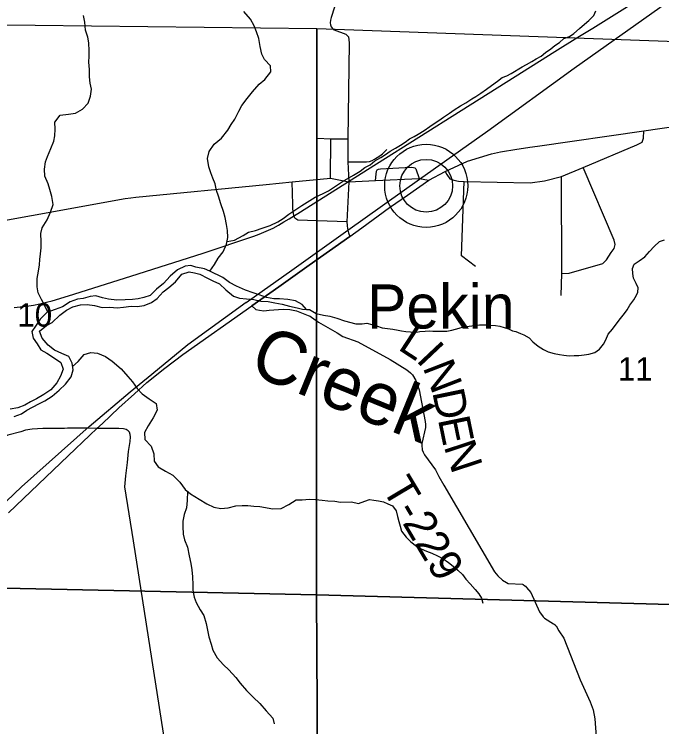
# Model space of a CAD drawing. Extents: x 0 to 34, y 0 to 22.
# Drawn here: x 3.716 to 4.875, y 15.27 to 16.545 of the extents above; entities that cross this region are included whole.
import ezdxf

# ---------------------------------------------------------------- set-up
doc = ezdxf.new("R2010")
doc.units = 0
doc.layers.add('Default', color=7, linetype='Continuous')

msp = doc.modelspace()

# ---------------------------------------------------------------- linework, layer by layer
at = {"layer": 'Default'}
for p, q in [((4.2817, 16.2516), (4.2827, 16.3216)), ((4.4533, 16.2382), (4.4533, 16.2382)), ((4.0219, 15.0104), (3.9291, 15.6027))]:
    msp.add_line(p, q, dxfattribs=at)
for points in [[(4.1345, 17.0111), (4.1482, 16.9849), (4.2622, 16.918), (4.2732, 16.9148), (4.2816, 16.9142), (4.341, 16.9149), (4.3454, 16.9137), (4.3498, 16.9116), (4.3533, 16.9088), (4.3596, 16.9011), (4.3625, 16.8954), (4.368, 16.8832), (4.3739, 16.8636), (4.3756, 16.8563), (4.3768, 16.846), (4.3762, 16.8394), (4.3746, 16.8279), (4.3721, 16.8159), (4.2834, 16.5397), (4.2818, 16.5345), (4.2813, 16.5302), (4.2818, 16.5266)], [(4.1311, 16.0292), (4.2125, 16.0873), (4.3131, 16.1587), (4.4414, 16.2501), (4.5633, 16.3368), (4.7182, 16.4485), (4.8857, 16.5673), (5.0019, 16.6486), (5.1164, 16.7282), (5.2393, 16.8153)], [(3.7156, 16.0206), (3.7263, 16.0214), (3.7379, 16.0226), (3.7504, 16.0245), (3.7616, 16.0267), (3.7736, 16.0296), (3.7838, 16.0323), (3.8128, 16.0412), (3.9246, 16.0764), (4.0541, 16.1175), (4.1445, 16.1478), (4.154, 16.1514), (4.1626, 16.1549), (4.1709, 16.1586), (4.1793, 16.1626), (4.1891, 16.1679), (4.1985, 16.1736), (4.2079, 16.179), (4.228, 16.1913), (4.2464, 16.2028), (4.3645, 16.2774), (4.5159, 16.3728), (4.6122, 16.4336), (4.6833, 16.4784), (4.7249, 16.504), (4.7515, 16.5202), (4.8736, 16.5975)], [(4.0662, 16.0852), (4.074, 16.0974), (4.081, 16.1085), (4.0895, 16.12), (4.096, 16.1338), (4.0981, 16.1456), (4.0975, 16.1581), (4.0955, 16.1687), (4.0934, 16.1815), (4.0902, 16.1924), (4.0854, 16.206), (4.0814, 16.2196), (4.0778, 16.2298), (4.0757, 16.2415), (4.0714, 16.2517), (4.0675, 16.2615), (4.0643, 16.272), (4.0618, 16.2868), (4.0646, 16.2997), (4.0738, 16.3127), (4.0865, 16.3235), (4.098, 16.3378), (4.1042, 16.3477), (4.1109, 16.3577), (4.1178, 16.3718), (4.1229, 16.3818), (4.1329, 16.3944), (4.1422, 16.4063), (4.1544, 16.4202), (4.1641, 16.4287), (4.1752, 16.4421), (4.1743, 16.4527), (4.1635, 16.4643), (4.1592, 16.4741), (4.1563, 16.4877), (4.1535, 16.5017), (4.1495, 16.5137), (4.1455, 16.5243), (4.1389, 16.5363), (4.1269, 16.5505)], [(4.3233, 16.2574), (4.3349, 16.2642), (4.3436, 16.2707), (4.353, 16.2758), (4.3612, 16.2828), (4.3718, 16.2886), (4.3801, 16.294), (4.3887, 16.2999), (4.3981, 16.3053), (4.4071, 16.3111), (4.4158, 16.3166), (4.4233, 16.3224), (4.4316, 16.3263), (4.4391, 16.3306), (4.4493, 16.3372), (4.4595, 16.3445), (4.4677, 16.35), (4.4756, 16.355), (4.4843, 16.3612), (4.4948, 16.3682), (4.5034, 16.3744), (4.5144, 16.3814), (4.5242, 16.3868), (4.5347, 16.3938), (4.5422, 16.3981), (4.5509, 16.4039), (4.561, 16.4109), (4.57, 16.4175), (4.5809, 16.4256), (4.5892, 16.4318), (4.5975, 16.435), (4.6054, 16.4392), (4.625, 16.4509), (4.6329, 16.4556), (4.6423, 16.4607), (4.6502, 16.4653), (4.6593, 16.47), (4.6668, 16.4766), (4.6762, 16.4832), (4.6833, 16.4893), (4.6916, 16.4948), (4.6998, 16.5017), (4.7096, 16.5053), (4.7175, 16.5107), (4.7277, 16.5196), (4.7367, 16.5273), (4.7446, 16.5339), (4.7532, 16.5431), (4.7568, 16.5515)], [(3.7762, 16.012), (3.771, 16.0223), (3.7643, 16.0347), (3.7588, 16.0468), (3.7571, 16.0574), (3.7569, 16.0725), (3.7593, 16.0855), (3.761, 16.0965), (3.7616, 16.106), (3.7626, 16.1166), (3.7639, 16.1272), (3.7641, 16.1378), (3.7631, 16.1526), (3.766, 16.1629), (3.7748, 16.1771), (3.7806, 16.1912), (3.7857, 16.2049), (3.7828, 16.2189), (3.7796, 16.2317), (3.7768, 16.2419), (3.7705, 16.2555), (3.7699, 16.268), (3.7716, 16.2813), (3.7756, 16.2908), (3.7814, 16.3049), (3.7869, 16.3183), (3.7886, 16.3278), (3.7888, 16.3395), (3.7886, 16.3521), (3.7982, 16.3647), (3.8129, 16.3665), (3.8257, 16.3682), (3.8377, 16.3752), (3.8481, 16.3864), (3.8524, 16.3986), (3.8541, 16.4111), (3.8517, 16.4217), (3.8507, 16.4331), (3.8505, 16.4463), (3.8495, 16.4596), (3.8497, 16.4702), (3.8499, 16.48), (3.8493, 16.4944), (3.8477, 16.5043), (3.8433, 16.5171), (3.8419, 16.5311), (3.8395, 16.5432)], [(4.2818, 16.5266), (4.2833, 16.523), (4.2839, 16.5222), (4.2856, 16.5199), (4.2884, 16.5174), (4.3091, 16.5096), (4.3141, 16.5047), (4.3151, 16.494), (4.313, 16.3218), (4.3132, 16.2809), (4.3145, 16.2453), (4.3114, 16.1734), (4.3116, 16.1672), (4.3121, 16.1609), (4.3144, 16.1542), (4.3166, 16.1475)], [(4.6523, 16.309), (4.8427, 16.3364), (4.9041, 16.3453), (4.9289, 16.3504), (4.9478, 16.3556), (4.9699, 16.364), (4.9932, 16.3745), (5.0136, 16.3866), (5.037, 16.4037), (5.0592, 16.4236), (5.0737, 16.4394), (5.0873, 16.4557), (5.1077, 16.4842)], [(2.7536, 16.3903), (2.9496, 16.3731), (3.0622, 16.4028), (3.0755, 16.4054), (3.0886, 16.4068), (3.1054, 16.4056), (3.1194, 16.4032), (3.1332, 16.3974), (3.1463, 16.3874), (3.161, 16.3732), (3.1758, 16.3541), (3.3304, 16.1487), (3.3378, 16.1413), (3.3458, 16.1357), (3.3589, 16.1287), (3.3749, 16.1245), (3.3922, 16.1234), (3.4105, 16.1244), (3.9144, 16.2154), (3.9245, 16.2165), (3.9335, 16.2176), (4.1665, 16.2407)], [(4.6394, 16.2438), (4.6653, 16.2471), (4.6956, 16.255), (4.7341, 16.2712), (4.83, 16.3114), (4.8396, 16.3164), (4.8423, 16.3232), (4.8427, 16.3364)], [(4.313, 16.3218), (4.2827, 16.3216), (4.2582, 16.3228)], [(4.3132, 16.2809), (4.3462, 16.2813), (4.3519, 16.2818), (4.3564, 16.2834), (4.3606, 16.2856), (4.3654, 16.2889), (4.37, 16.2919), (4.3752, 16.2956), (4.3825, 16.3031)], [(4.5863, 16.2989), (4.5901, 16.2997), (4.6118, 16.3032), (4.639, 16.3071), (4.6523, 16.309)], [(4.3166, 16.1475), (4.3383, 16.1629), (4.3873, 16.1991), (4.4195, 16.2212), (4.4582, 16.2482), (4.4869, 16.2639), (4.5271, 16.2822), (4.5486, 16.289), (4.5701, 16.2953), (4.5863, 16.2989)], [(4.3627, 16.2476), (4.3634, 16.2593), (4.3644, 16.2646), (4.3656, 16.2666), (4.3666, 16.2672), (4.368, 16.2678), (4.3717, 16.2685), (4.4261, 16.2714), (4.4307, 16.2712), (4.4329, 16.2704), (4.4346, 16.2688), (4.4404, 16.2513)], [(4.4869, 16.2639), (4.4901, 16.2584), (4.4956, 16.2509), (4.5029, 16.248), (4.5109, 16.2465), (4.5212, 16.2459), (4.6394, 16.2438)], [(4.7692, 16.0988), (4.776, 16.1058), (4.7846, 16.1186), (4.7896, 16.1258), (4.7916, 16.1333), (4.7896, 16.1409), (4.7341, 16.2712)], [(4.0968, 16.1382), (4.1099, 16.1408), (4.1256, 16.1491), (4.1354, 16.1549), (4.1474, 16.1581), (4.1598, 16.1625), (4.1741, 16.1669), (4.1876, 16.1736), (4.1973, 16.1798), (4.2074, 16.1872), (4.2179, 16.1945), (4.2306, 16.2031), (4.2448, 16.212), (4.2545, 16.2179), (4.2688, 16.2245), (4.2785, 16.2293), (4.2927, 16.239), (4.3032, 16.246), (4.3233, 16.2574)], [(4.1665, 16.2407), (4.2133, 16.2453), (4.2817, 16.2516), (4.3145, 16.2453), (4.3627, 16.2476), (4.4404, 16.2513), (4.4582, 16.2482)], [(4.6951, 16.042), (4.6958, 16.0812), (4.6956, 16.255)], [(4.216, 16.1852), (4.2143, 16.1969), (4.2143, 16.2046), (4.2133, 16.2453)], [(4.5415, 16.0936), (4.5166, 16.1128), (4.5212, 16.2459)], [(4.3114, 16.1734), (4.2233, 16.1766), (4.218, 16.1802), (4.216, 16.1852)], [(4.1412, 16.0232), (4.1895, 16.0571), (4.2435, 16.096), (4.3166, 16.1475)], [(4.3166, 16.1475), (4.2435, 16.096), (4.1895, 16.0571), (4.1412, 16.0232)], [(4.3274, 15.991), (4.3385, 15.9911), (4.3472, 15.9921), (4.356, 15.9896), (4.3644, 15.9874), (4.3747, 15.9842), (4.3842, 15.9828), (4.3937, 15.9818), (4.4029, 15.98), (4.4089, 15.9786), (4.4169, 15.9772), (4.4253, 15.9765), (4.4363, 15.9763), (4.442, 15.9771), (4.4511, 15.978), (4.4595, 15.9785), (4.4652, 15.9782), (4.475, 15.978), (4.4842, 15.9777), (4.4899, 15.9778), (4.4993, 15.9799), (4.5122, 15.9835), (4.5201, 15.9855), (4.53, 15.9868), (4.5395, 15.988), (4.5485, 15.9893), (4.5546, 15.9894), (4.5634, 15.9891), (4.5691, 15.9888), (4.5774, 15.9882), (4.585, 15.9868), (4.5927, 15.9846), (4.6003, 15.9821), (4.6079, 15.9788), (4.6137, 15.9773), (4.6221, 15.974), (4.6278, 15.9711), (4.6374, 15.9659), (4.6443, 15.9591), (4.6539, 15.9513), (4.6631, 15.9454), (4.6715, 15.9409), (4.6822, 15.938), (4.6917, 15.9363), (4.6997, 15.9349), (4.7092, 15.9339), (4.7183, 15.9344), (4.7267, 15.9345), (4.7362, 15.9354), (4.7445, 15.9367), (4.7551, 15.9398), (4.7634, 15.946), (4.7705, 15.9545), (4.7749, 15.9625), (4.7789, 15.9725), (4.7868, 15.9817), (4.7931, 15.9905), (4.8009, 16.0005), (4.8084, 16.0097), (4.8128, 16.0162), (4.818, 16.0246), (4.8251, 16.0342), (4.8299, 16.0423), (4.8318, 16.048), (4.8324, 16.0556), (4.8292, 16.0635), (4.8246, 16.073), (4.8233, 16.0813), (4.8224, 16.09), (4.8257, 16.098), (4.8347, 16.1039), (4.8445, 16.1108), (4.8531, 16.1208), (4.8613, 16.1293), (4.8711, 16.1385), (4.8798, 16.1417)], [(4.6958, 16.0812), (4.7094, 16.0817), (4.7692, 16.0988)], [(4.2387, 16.0168), (4.2312, 16.0258), (4.219, 16.0321), (4.2057, 16.0345), (4.1909, 16.0358), (4.1807, 16.036), (4.1671, 16.038), (4.1542, 16.0427), (4.1435, 16.0463), (4.1295, 16.0514), (4.1135, 16.0587), (4.1013, 16.0649), (4.089, 16.0742), (4.0661, 16.0852), (4.0562, 16.0896), (4.0411, 16.0927), (4.0316, 16.0956), (4.0218, 16.0943), (4.0083, 16.0876), (3.9949, 16.0764), (3.983, 16.0633), (3.9707, 16.0529), (3.9588, 16.0417), (3.9475, 16.0385), (3.9374, 16.036), (3.9276, 16.0347), (3.9144, 16.0341), (3.8992, 16.0335), (3.8845, 16.0351), (3.8739, 16.0376), (3.8617, 16.0412), (3.8519, 16.0399), (3.8391, 16.0367), (3.8289, 16.035), (3.8158, 16.0306), (3.8023, 16.0216), (3.7892, 16.0165), (3.7742, 16.0113), (3.7619, 15.9993), (3.7538, 15.9871), (3.7472, 15.9775), (3.7496, 15.9654), (3.7566, 15.9553), (3.7636, 15.9444), (3.7739, 15.9385), (3.7858, 15.9307), (3.7991, 15.9219), (3.8035, 15.9102), (3.7988, 15.8976), (3.7918, 15.8857), (3.7811, 15.873), (3.7687, 15.8645), (3.7556, 15.8571), (3.7448, 15.8516), (3.7347, 15.8457), (3.7223, 15.8406), (3.7087, 15.8381)], [(3.7158, 15.8253), (3.7285, 15.8301), (3.7382, 15.8367), (3.76, 15.848), (3.7708, 15.8532), (3.7835, 15.8617), (3.7962, 15.8722), (3.8077, 15.883), (3.8177, 15.8964), (3.8213, 15.909), (3.8192, 15.9207), (3.8137, 15.9324), (3.8007, 15.9382), (3.7878, 15.9437), (3.7763, 15.9526), (3.7655, 15.9653), (3.7611, 15.9777), (3.7738, 15.9882), (3.7839, 15.9936), (3.7973, 16.0068), (3.8092, 16.0157), (3.8205, 16.0216), (3.8344, 16.0252), (3.8465, 16.0258), (3.8597, 16.0237), (3.873, 16.0205), (3.887, 16.0208), (3.9002, 16.0199), (3.9112, 16.0212), (3.9248, 16.0226), (3.9357, 16.0224), (3.9485, 16.0241), (3.9613, 16.0292), (3.9718, 16.0366), (3.9825, 16.0482), (3.9926, 16.0559), (4.0045, 16.0664), (4.016, 16.0798), (4.0291, 16.0842), (4.0386, 16.0825), (4.0481, 16.08), (4.0615, 16.0726), (4.071, 16.0679), (4.0832, 16.0627), (4.0947, 16.0519), (4.1085, 16.0408), (4.1191, 16.0368), (4.1316, 16.0359)], [(4.1316, 16.0359), (4.1445, 16.0346), (4.1574, 16.0314), (4.1702, 16.0309), (4.182, 16.0284), (4.1953, 16.026), (4.2086, 16.0228), (4.2222, 16.0196), (4.2317, 16.0175), (4.2387, 16.0168)], [(2.9993, 14.9996), (3.3253, 15.3142), (3.7288, 15.6994), (3.8497, 15.8071), (3.923, 15.8692), (3.9623, 15.9011), (4.0263, 15.9543), (4.1309, 16.0297)], [(3.8638, 15.8037), (3.8735, 15.8126), (3.9029, 15.8405), (3.931, 15.866), (3.9532, 15.8858), (3.9853, 15.9119), (4.0176, 15.9361), (4.1412, 16.0232)], [(4.1412, 16.0232), (4.1483, 16.017), (4.155, 16.0153), (4.1627, 16.0146), (4.1722, 16.0156), (4.1973, 16.0175), (4.209, 16.0168), (4.2209, 16.0143), (4.2417, 16.0061), (4.2454, 16.0046), (4.2479, 16.003), (4.2605, 15.9943), (4.2939, 15.9748), (4.3039, 15.9682), (4.3306, 15.9588), (4.3888, 15.9271), (4.4187, 15.9088), (4.4252, 15.9036), (4.4287, 15.8998), (4.4344, 15.8896), (4.4384, 15.8794), (4.4404, 15.8732), (4.4513, 15.8163), (4.452, 15.8108), (4.4522, 15.8056), (4.4456, 15.7771), (4.4455, 15.7737), (4.4461, 15.7656), (4.4477, 15.7612), (4.45, 15.7566), (4.4698, 15.7294), (4.4756, 15.7176), (4.4845, 15.7025), (4.5757, 15.5471), (4.5813, 15.5401), (4.5896, 15.5324), (4.5968, 15.5279), (4.5999, 15.5264), (4.6255, 15.5248), (4.6263, 15.5245), (4.6269, 15.5242), (4.628, 15.5235), (4.6307, 15.5212), (4.6328, 15.5191), (4.6405, 15.5101), (4.6561, 15.4756), (4.6625, 15.4666), (4.665, 15.4643), (4.6812, 15.4542), (4.6833, 15.4527), (4.6843, 15.4519), (4.6856, 15.4502), (4.6907, 15.4413), (4.6996, 15.4285), (4.7286, 15.3535), (4.7469, 15.3141), (4.7524, 15.3001), (4.7553, 15.2841), (4.7664, 15.1324)], [(4.2387, 16.0168), (4.2442, 16.0166), (4.2564, 16.0096), (4.2693, 16.0067), (4.281, 16.005), (4.2932, 16.0015), (4.3069, 15.9964), (4.3274, 15.991)], [(3.8203, 15.9146), (3.8305, 15.9239), (3.8408, 15.9362), (3.8529, 15.9395), (3.865, 15.9385), (3.8791, 15.9327), (3.8913, 15.9242), (3.9074, 15.9104), (3.919, 15.897), (3.9275, 15.8873), (3.936, 15.8753), (3.9448, 15.8656), (3.9575, 15.8567), (3.9697, 15.8485), (3.9714, 15.8368), (3.9645, 15.8227), (3.9556, 15.8085), (3.9487, 15.7963), (3.9496, 15.7841), (3.9608, 15.7718), (3.9659, 15.7586), (3.9662, 15.7454), (3.9735, 15.7349), (3.9865, 15.7271), (3.9999, 15.7202), (4.0122, 15.7075), (4.0215, 15.6947), (4.0314, 15.6869), (4.0467, 15.6773), (4.0604, 15.6689), (4.073, 15.663), (4.0855, 15.6602), (4.0987, 15.6619), (4.1123, 15.6652), (4.124, 15.6658), (4.1338, 15.6659), (4.1448, 15.6646), (4.1554, 15.664), (4.1789, 15.6599), (4.1936, 15.6605), (4.2075, 15.6679), (4.2206, 15.6757), (4.2311, 15.6759), (4.2443, 15.6773), (4.2549, 15.6767), (4.267, 15.6754), (4.2769, 15.6744), (4.2897, 15.6735), (4.2996, 15.6721), (4.3197, 15.6723), (4.3323, 15.6692)], [(3.8112, 15.8044), (3.8059, 15.8039), (3.792, 15.8039), (3.7672, 15.8039), (3.748, 15.8024), (3.736, 15.8005), (3.7276, 15.7978), (3.7042, 15.792), (3.6942, 15.7876), (3.6843, 15.7795), (3.6794, 15.7746), (3.673, 15.7633), (3.6659, 15.7496), (3.6593, 15.7364), (3.654, 15.7279), (3.6486, 15.7161), (3.644, 15.7126), (3.637, 15.7131), (3.6303, 15.7168), (3.6259, 15.7198), (3.6204, 15.7228), (3.6129, 15.7265), (3.5899, 15.7424)], [(3.9291, 15.6027), (3.914, 15.6991), (3.9156, 15.7192), (3.9184, 15.7427), (3.9204, 15.7624), (3.9232, 15.7803), (3.9238, 15.7885), (3.9235, 15.7927), (3.922, 15.7973), (3.9198, 15.7993), (3.9164, 15.8022), (3.9116, 15.8033), (3.9031, 15.8035), (3.8638, 15.8037), (3.8491, 15.8044), (3.8345, 15.8045), (3.8238, 15.8045), (3.8133, 15.8045), (3.8112, 15.8044)], [(3.7055, 15.6525), (3.8122, 15.7547), (3.8512, 15.7919), (3.8638, 15.8037)], [(4.0257, 15.6914), (4.0252, 15.6747), (4.0243, 15.6618), (4.02, 15.65), (4.0175, 15.6378), (4.0177, 15.628), (4.0183, 15.6147), (4.0207, 15.6045), (4.0262, 15.5913), (4.0292, 15.5758), (4.0317, 15.5618), (4.0334, 15.5509), (4.0347, 15.5384), (4.0353, 15.524), (4.0355, 15.5141), (4.0376, 15.5017), (4.0412, 15.4919), (4.0486, 15.4791), (4.0552, 15.469), (4.0592, 15.4543), (4.0617, 15.4429), (4.0641, 15.4308), (4.0681, 15.4176), (4.0714, 15.4067), (4.0788, 15.3932), (4.0903, 15.3808), (4.0999, 15.3719), (4.1123, 15.3577), (4.12, 15.348), (4.1315, 15.3345), (4.1435, 15.3226), (4.1557, 15.3114), (4.1669, 15.298), (4.1785, 15.2849), (4.1813, 15.2751)], [(4.3323, 15.6692), (4.3431, 15.6737), (4.3518, 15.6763), (4.3594, 15.6753), (4.3678, 15.6742), (4.3766, 15.6725), (4.3846, 15.6688), (4.393, 15.6655), (4.3996, 15.6565), (4.402, 15.6463), (4.404, 15.6372), (4.4064, 15.6289), (4.4092, 15.6198), (4.4174, 15.6093), (4.4258, 15.601), (4.4358, 15.5932), (4.4442, 15.5884), (4.4538, 15.584), (4.4633, 15.5803), (4.4737, 15.5759), (4.4829, 15.5707), (4.4932, 15.564), (4.5017, 15.5573), (4.5101, 15.5498), (4.5182, 15.5424), (4.524, 15.5341), (4.5317, 15.5255), (4.5406, 15.5157), (4.5476, 15.5078), (4.5522, 15.4999), (4.5546, 15.4912)]]:
    msp.add_lwpolyline(points, dxfattribs=at)
for points in [[(3.2485, 16.532), (4.2574, 16.5198), (4.2566, 15.5062), (3.2514, 15.5272)], [(4.2574, 16.5198), (5.2975, 16.482), (5.284, 15.4777), (4.2566, 15.5062)], [(4.2566, 15.5062), (4.2629, 14.5006), (3.2648, 14.5009), (3.2514, 15.5272)], [(4.2566, 15.5062), (5.284, 15.4777), (5.2822, 14.472), (4.2629, 14.5006)]]:
    msp.add_lwpolyline(points, close=True, dxfattribs=at)
for radius in [0.0744, 0.0472]:
    msp.add_circle((4.4533, 16.2382), radius, dxfattribs=at)

# ---------------------------------------------------------------- texts
for s, height, rotation, p in [('Pekin', 0.07898, 0, (4.3473, 15.9827)), ('10', 0.04186, 0, (3.7214, 15.9861)), ('L', 0.0568, 326.8389, (4.4007, 15.9464)), ('Creek', 0.09472, 337.8115, (4.1325, 15.9038)), ('I', 0.0568, 313.2997, (4.4336, 15.9255)), ('N', 0.0568, 291.1107, (4.4465, 15.9134)), ('11', 0.04186, 0, (4.7964, 15.8894)), ('D', 0.0568, 281.7386, (4.4638, 15.8691)), ('E', 0.0568, 281.647, (4.474, 15.8202)), ('N', 0.0568, 288.1666, (4.4843, 15.7718)), ('T-229', 0.05682, 300.7835, (4.373, 15.6964))]:
    msp.add_text(s, height=height, rotation=rotation, dxfattribs=at).set_placement(p)

doc.saveas('drawing.dxf')
